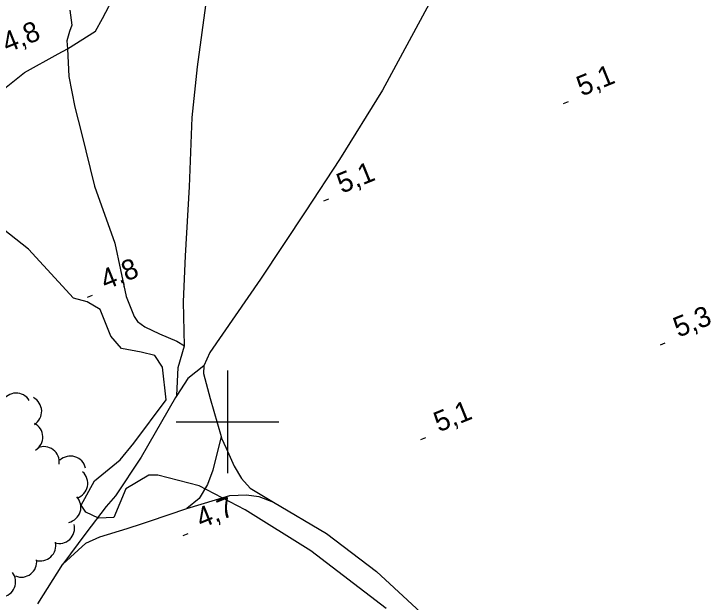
# Model space of a CAD drawing. Extents: x 362852 to 366875, y 5563573 to 5566479.
# Drawn here: x 364158.5 to 364294, y 5565364.9 to 5565479.3 of the extents above; entities that cross this region are included whole.
import ezdxf

# ---------------------------------------------------------------- set-up
doc = ezdxf.new("R2010")
doc.units = 0
for name, color, linetype in [('Niveau 22', 7, 'Continuous'), ('Niveau 3', 7, 'Continuous'), ('Niveau 44', 7, 'Continuous'), ('Niveau 61', 7, 'Continuous'), ('Niveau 7', 7, 'Continuous')]:
    doc.layers.add(name, color=color, linetype=linetype)

msp = doc.modelspace()

# ---------------------------------------------------------------- linework, layer by layer
at = {"layer": 'Niveau 22'}
for points in [[(364190.14, 5565405.14), (364190.41, 5565410.55), (364191.65, 5565414.78), (364191.45, 5565423.32), (364191.84, 5565432.29), (364192.59, 5565445.73), (364193.11, 5565459.15), (364194.19, 5565469.03), (364195.96, 5565482.46), (364197.31, 5565490.56), (364197.61, 5565501.76), (364199.19, 5565508.83), (364199.76, 5565511.96), (364201.02, 5565519.02), (364201.67, 5565530.75), (364202.97, 5565539.79), (364205.3, 5565551.39), (364205.87, 5565563.47), (364207.52, 5565578.14), (364209.66, 5565593.64), (364211.41, 5565610.88), (364213.57, 5565623.55), (364214.01, 5565626.51)], [(364126.67, 5565442.63), (364130.43, 5565444.93), (364134.94, 5565447.73), (364139.52, 5565451.56), (364141.39, 5565452.83), (364143.95, 5565453.76), (364146.38, 5565454.57), (364148.84, 5565455.45), (364149.74, 5565456.46), (364155.25, 5565463.76), (364160.5, 5565467.93), (364167.05, 5565471.56), (364168.87, 5565472.52), (364174.36, 5565475.98), (364175.69, 5565478.41), (364178.22, 5565483.29)], [(364239.21, 5565481.26), (364230.12, 5565464.48), (364221.81, 5565451.04), (364215.21, 5565441), (364206.44, 5565427.71), (364196.56, 5565413.47), (364195.42, 5565410.87), (364195.33, 5565409.38), (364196.6, 5565404.56), (364198.76, 5565397.13)], [(364169.32, 5565480.07), (364169.7, 5565477.14), (364169.26, 5565475.9), (364168.78, 5565474.12), (364168.87, 5565472.52), (364169.16, 5565467.16), (364170.31, 5565461.22), (364171.6, 5565456.15), (364174.16, 5565445.82), (364178.08, 5565434.73), (364180.32, 5565424.39), (364181.84, 5565420.49), (364182.49, 5565419.5), (364183.91, 5565418.45), (364186.77, 5565417.1), (364190.16, 5565415.67), (364191.65, 5565414.78)], [(364195.42, 5565410.87), (364192.27, 5565408.43), (364190.14, 5565405.14)], [(364190.14, 5565405.14), (364189.89, 5565404.74), (364183.2, 5565393.12), (364178.22, 5565385.6), (364176.43, 5565383.52), (364172.47, 5565378.31), (364167.98, 5565372.31)], [(364198.76, 5565397.13), (364197.18, 5565390.59), (364196.11, 5565387.83), (364194.52, 5565385.09), (364192.11, 5565383.14)], [(364198.76, 5565397.13), (364198.85, 5565396.81), (364199.77, 5565394.86), (364201.29, 5565391.4), (364202.71, 5565388.98), (364204.41, 5565387.11), (364208.95, 5565384.37)], [(364163.11, 5565364.61), (364167.98, 5565372.31), (364172.45, 5565376.37), (364175.19, 5565377.63), (364180.48, 5565379.22), (364183.47, 5565380.19), (364184.83, 5565380.69), (364192.11, 5565383.14), (364200.43, 5565385.64), (364203.68, 5565385.79), (364206.07, 5565385.45), (364208.95, 5565384.37), (364219.24, 5565378.26), (364228.97, 5565370.87), (364238.43, 5565362.15)]]:
    msp.add_lwpolyline(points, dxfattribs=at)
at = {"layer": 'Niveau 3'}
for p, q in [((364265.37, 5565461.89), (364266.33, 5565462.28)), ((364218.72, 5565442.99), (364219.68, 5565443.38)), ((364172.78, 5565424.26), (364173.74, 5565424.65)), ((364284.18, 5565414.99), (364285.14, 5565415.38)), ((364237.59, 5565396.57), (364238.55, 5565396.96)), ((364191.39, 5565377.89), (364192.35, 5565378.28))]:
    msp.add_line(p, q, dxfattribs=at)
at = {"layer": 'Niveau 44'}
for centre, start, end in [((364158.9, 5565402.58), 31.76, 151.7379), ((364160.87, 5565402.04), 302.3505, 62.3284), ((364161.08, 5565397.04), 302.3505, 62.3284), ((364164.28, 5565392.17), 352.7114, 112.6894), ((364169.47, 5565390.33), 13.1328, 133.1107), ((364169.83, 5565388.03), 288.5106, 48.4886), ((364168.49, 5565383.37), 282.6955, 42.6734), ((364167.28, 5565379.34), 252.8814, 12.8593), ((364163.61, 5565375.94), 252.8814, 12.8593), ((364159.91, 5565372.79), 247.5847, 7.5626), ((364155.79, 5565368.89), 277.5691, 37.5471)]:
    msp.add_arc(centre, 3, start, end, dxfattribs=at)
at = {"layer": 'Niveau 61'}
for p, q in [((364200, 5565410), (364200, 5565390)), ((364190, 5565400), (364210, 5565400))]:
    msp.add_line(p, q, dxfattribs=at)
at = {"layer": 'Niveau 7'}
msp.add_lwpolyline([(364230.88, 5565363.69), (364216.23, 5565374.88), (364203.46, 5565382.91), (364194.47, 5565387.52), (364186.47, 5565389.6), (364184.71, 5565389.63), (364180.24, 5565386.99), (364177.88, 5565381.38), (364174.91, 5565381.29), (364172.46, 5565382.42), (364171.52, 5565383.79), (364174.13, 5565388.55), (364179.12, 5565392.61), (364181.81, 5565395.85), (364188.08, 5565404.25), (364187.38, 5565410.63), (364185.84, 5565412.89), (364183.19, 5565413.56), (364179.4, 5565414.27), (364177.3, 5565416.67), (364175.21, 5565421.85), (364172.73, 5565423.35), (364170.08, 5565424.02), (364161.3, 5565433.59), (364151.41, 5565441.35)], dxfattribs=at)

# ---------------------------------------------------------------- texts
at = {"layer": 'Niveau 3'}
for s, p in [('4,8  ', (364157.15, 5565471.73)), ('5,1  ', (364268.88, 5565463.25)), ('5,1  ', (364222.23, 5565444.35)), ('4,8  ', (364176.29, 5565425.62)), ('5,3  ', (364287.69, 5565416.35)), ('5,1  ', (364241.1, 5565397.93)), ('4,7  ', (364194.9, 5565379.25))]:
    msp.add_text(s, height=3.93, rotation=22.09, dxfattribs=at).set_placement(p)

doc.saveas('drawing.dxf')
